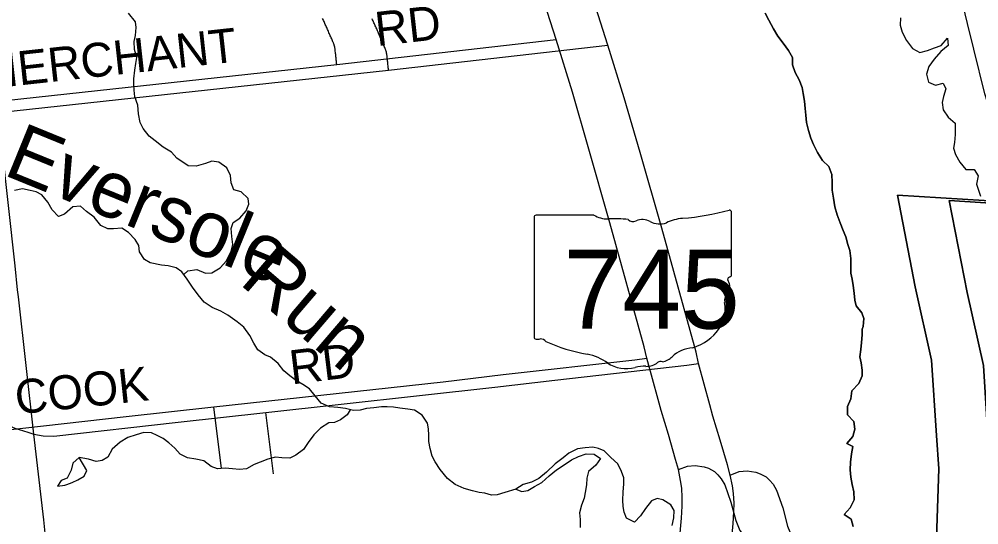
# Model space of a CAD drawing. Extents: x -38.2 to 41.9, y -4 to 24.9.
# Drawn here: x 2.823 to 4.425, y 18.738 to 19.582 of the extents above; entities that cross this region are included whole.
import ezdxf

# ---------------------------------------------------------------- set-up
doc = ezdxf.new("R2010")
doc.units = 0
for name, color, linetype in [('GM_X_Interchange_Ramps', 7, 'Continuous'), ('GM_X_Major_Lake', 7, 'Continuous'), ('GM_X_Major_River', 7, 'Continuous'), ('GM_X_Minor_Lake', 7, 'Continuous'), ('GM_X_Minor_River', 7, 'Continuous'), ('GM_X_Minor_River_Text', 7, 'Continuous'), ('GM_X_State_Location', 7, 'Continuous'), ('GM_X_State_Route', 7, 'Continuous'), ('GM_X_State_Shield', 7, 'Continuous'), ('GM_X_Township_Road', 7, 'Continuous'), ('GM_X_Township_Road_Text', 7, 'Continuous')]:
    doc.layers.add(name, color=color, linetype=linetype)

msp = doc.modelspace()

# ---------------------------------------------------------------- linework, layer by layer
at = {"layer": 'GM_X_Interchange_Ramps'}
for points in [[(8.9, 20.9), (5.1243, 20.9), (5.0869, 20.3321), (5.0183, 19.2401), (4.524, 19.2724), (4.5063, 19.2749), (4.2891, 19.2883), (4.3187, 19.1351), (4.3461, 19.0129), (4.3543, 18.8869), (4.3579, 18.8315), (4.3427, 18.3695), (4.3427, 18.2191), (4.3507, 18.0744), (4.3697, 17.9734), (4.4043, 17.861), (4.5071, 17.5648), (4.5129, 17.5446), (4.531, 17.482), (4.5322, 17.4318), (4.517, 17.3994), (4.4957, 17.354), (4.5219, 17.2005)], [(8.9, 20.9), (5.2114, 20.9), (5.1734, 20.3229), (5.1048, 19.2309), (4.6105, 19.2632), (4.5928, 19.2657), (4.3756, 19.2791), (4.4052, 19.1259), (4.4326, 19.0037), (4.4408, 18.8777), (4.4444, 18.8223), (4.4292, 18.3603), (4.4292, 18.2099), (4.4372, 18.0652), (4.4562, 17.9642), (4.4908, 17.8518), (4.5935, 17.5556), (4.5994, 17.5354), (4.6175, 17.4728), (4.6186, 17.4226), (4.6035, 17.3903), (4.5821, 17.3448), (4.6084, 17.1913)], [(4.5219, 17.2005), (4.4957, 17.354), (4.517, 17.3994), (4.5322, 17.4318), (4.531, 17.482), (4.5129, 17.5446), (4.5071, 17.5648), (4.4043, 17.861), (4.3697, 17.9734), (4.3507, 18.0744), (4.3427, 18.2191), (4.3427, 18.3695), (4.3579, 18.8315), (4.3543, 18.8869), (4.3461, 19.0129), (4.3187, 19.1351), (4.2891, 19.2883), (4.5063, 19.2749), (4.524, 19.2724), (5.0183, 19.2401), (5.0869, 20.3321)], [(4.6084, 17.1913), (4.5821, 17.3448), (4.6035, 17.3903), (4.6186, 17.4226), (4.6175, 17.4728), (4.5994, 17.5354), (4.5935, 17.5556), (4.4908, 17.8518), (4.4562, 17.9642), (4.4372, 18.0652), (4.4292, 18.2099), (4.4292, 18.3603), (4.4444, 18.8223), (4.4408, 18.8777), (4.4326, 19.0037), (4.4052, 19.1259), (4.3756, 19.2791), (4.5928, 19.2657), (4.6105, 19.2632), (5.1048, 19.2309), (5.1734, 20.3229)], [(3.9757, 18.9381), (3.9569, 19.007), (3.9527, 19.026), (3.8955, 19.2331), (3.8592, 19.3597), (3.8326, 19.4508), (3.8055, 19.539), (3.714, 19.8259), (3.6685, 19.9614), (3.651, 20.0166), (3.6474, 20.0308), (3.6447, 20.045), (3.636, 20.0869), (3.6248, 20.1343), (3.61, 20.2076), (3.6064, 20.2246), (3.6031, 20.2385), (3.5987, 20.261), (3.5926, 20.2977)], [(3.9994, 18.3639), (3.9915, 18.4341), (3.9915, 18.4746), (3.9931, 18.514), (4.0114, 18.7026), (4.0149, 18.7399), (4.0161, 18.7595), (4.0162, 18.7742), (4.0153, 18.7899), (4.0135, 18.8027), (4.0097, 18.8208), (4.005, 18.8379), (3.9931, 18.8793), (3.9808, 18.9194), (3.9757, 18.9381)]]:
    msp.add_lwpolyline(points, dxfattribs=at)
at = {"layer": 'GM_X_Major_Lake'}
for points in [[(4.2319, 19.0689), (4.2327, 19.0822), (4.2297, 19.0917), (4.2203, 19.1035), (4.2177, 19.113), (4.2166, 19.1244), (4.2151, 19.1377), (4.2133, 19.1479), (4.2114, 19.1578), (4.2111, 19.1691), (4.2112, 19.1824), (4.2093, 19.1961), (4.2063, 19.2059), (4.2026, 19.2188), (4.1985, 19.2291), (4.1932, 19.242), (4.1883, 19.2557), (4.1846, 19.269), (4.182, 19.2834), (4.1801, 19.2967), (4.1798, 19.3092), (4.1795, 19.3228), (4.1743, 19.3361), (4.1637, 19.3464), (4.1557, 19.3597), (4.149, 19.373), (4.1445, 19.3832), (4.1407, 19.3965), (4.1374, 19.4098), (4.1359, 19.4219), (4.1348, 19.4329), (4.1341, 19.4454), (4.1315, 19.4583), (4.1297, 19.4682), (4.1252, 19.4807), (4.1184, 19.4929), (4.1139, 19.5058), (4.1136, 19.5179), (4.1072, 19.5297), (4.0985, 19.5423), (4.0894, 19.554), (4.0819, 19.5662), (4.0743, 19.5803), (4.0683, 19.592)], [(4.2939, 19.5845), (4.2934, 19.572), (4.2968, 19.5603), (4.3043, 19.5466), (4.3142, 19.5333), (4.3263, 19.5264), (4.3392, 19.5298), (4.351, 19.5343), (4.362, 19.538), (4.3727, 19.5505), (4.3738, 19.5383), (4.3616, 19.5281), (4.3502, 19.5153), (4.3414, 19.5032), (4.3375, 19.4904), (4.3409, 19.4767), (4.3526, 19.4717), (4.3652, 19.4751), (4.3701, 19.4656), (4.3662, 19.4531), (4.3639, 19.4432), (4.3653, 19.4307), (4.374, 19.4186), (4.3857, 19.4087), (4.3853, 19.3992), (4.3857, 19.3893), (4.3845, 19.3764), (4.3825, 19.3666), (4.3859, 19.3564), (4.3934, 19.3434), (4.4032, 19.3309), (4.4169, 19.3312), (4.4237, 19.3205), (4.421, 19.3069), (4.4277, 19.2864)], [(4.2152, 18.7349), (4.2119, 18.747), (4.2001, 18.7551), (4.2101, 18.7664), (4.2166, 18.7796), (4.2163, 18.7929), (4.2133, 18.8054), (4.2114, 18.8172), (4.21, 18.8294), (4.2108, 18.8426), (4.2124, 18.8563), (4.2147, 18.8684), (4.2048, 18.8734), (4.2144, 18.8851), (4.2179, 18.8976), (4.2164, 18.9101), (4.2058, 18.9215), (4.2055, 18.9356), (4.2112, 18.9484), (4.2128, 18.9617), (4.2243, 18.9738), (4.23, 18.9867), (4.2304, 18.9961), (4.2286, 19.0083), (4.2264, 19.0182), (4.2279, 19.0303), (4.2288, 19.0424), (4.2299, 19.0549), (4.23, 19.0644), (4.2319, 19.0689)]]:
    msp.add_lwpolyline(points, dxfattribs=at)
at = {"layer": 'GM_X_Major_River'}
for points in [[(4.0683, 19.592), (4.0743, 19.5803), (4.0819, 19.5662), (4.0894, 19.554), (4.0985, 19.5423), (4.1072, 19.5297), (4.1136, 19.5179), (4.1139, 19.5058), (4.1184, 19.4929), (4.1252, 19.4807), (4.1297, 19.4682), (4.1315, 19.4583), (4.1341, 19.4454), (4.1348, 19.4329), (4.1359, 19.4219), (4.1374, 19.4098), (4.1407, 19.3965), (4.1445, 19.3832), (4.149, 19.373), (4.1557, 19.3597), (4.1637, 19.3464), (4.1743, 19.3361), (4.1795, 19.3228), (4.1798, 19.3092), (4.1801, 19.2967), (4.182, 19.2834), (4.1846, 19.269), (4.1883, 19.2557), (4.1932, 19.242), (4.1985, 19.2291), (4.2026, 19.2188), (4.2063, 19.2059), (4.2093, 19.1961), (4.2112, 19.1824), (4.2111, 19.1691), (4.2114, 19.1578), (4.2133, 19.1479), (4.2151, 19.1377), (4.2166, 19.1244), (4.2177, 19.113), (4.2203, 19.1035), (4.2297, 19.0917), (4.2327, 19.0822), (4.2319, 19.0689)], [(4.2939, 19.5845), (4.2934, 19.572), (4.2968, 19.5603), (4.3043, 19.5466), (4.3142, 19.5333), (4.3263, 19.5264), (4.3392, 19.5298), (4.351, 19.5343), (4.362, 19.538), (4.3727, 19.5505), (4.3738, 19.5383), (4.3616, 19.5281), (4.3502, 19.5153), (4.3414, 19.5032), (4.3375, 19.4904), (4.3409, 19.4767), (4.3526, 19.4717), (4.3652, 19.4751), (4.3701, 19.4656), (4.3662, 19.4531), (4.3639, 19.4432), (4.3653, 19.4307), (4.374, 19.4186), (4.3857, 19.4087), (4.3853, 19.3992), (4.3857, 19.3893), (4.3845, 19.3764), (4.3825, 19.3666), (4.3859, 19.3564), (4.3934, 19.3434), (4.4032, 19.3309), (4.4169, 19.3312), (4.4237, 19.3205), (4.421, 19.3069), (4.4277, 19.2864)], [(4.2319, 19.0689), (4.23, 19.0644), (4.2299, 19.0549), (4.2288, 19.0424), (4.2279, 19.0303), (4.2264, 19.0182), (4.2286, 19.0083), (4.2304, 18.9961), (4.23, 18.9867), (4.2243, 18.9738), (4.2128, 18.9617), (4.2112, 18.9484), (4.2055, 18.9356), (4.2058, 18.9215), (4.2164, 18.9101), (4.2179, 18.8976), (4.2144, 18.8851), (4.2048, 18.8734), (4.2147, 18.8684), (4.2124, 18.8563), (4.2108, 18.8426), (4.21, 18.8294), (4.2114, 18.8172), (4.2133, 18.8054), (4.2163, 18.7929), (4.2166, 18.7796), (4.2101, 18.7664), (4.2001, 18.7551), (4.2119, 18.747), (4.2152, 18.7349)], [(3.9127, 18.7368), (3.9158, 18.7493), (3.9162, 18.7618), (3.9105, 18.7713), (3.8973, 18.7797), (3.8878, 18.782), (3.8783, 18.7779), (3.8684, 18.765), (3.86, 18.7529), (3.8497, 18.7423), (3.8368, 18.7492), (3.8327, 18.759), (3.8308, 18.7685), (3.8304, 18.7792), (3.8312, 18.7921), (3.832, 18.8061), (3.8321, 18.8163), (3.8283, 18.827), (3.8219, 18.8399), (3.8105, 18.8505), (3.7995, 18.8612), (3.7901, 18.865), (3.7802, 18.8677), (3.7677, 18.8666), (3.7548, 18.8647), (3.7403, 18.8572), (3.7308, 18.8496), (3.7175, 18.8394), (3.703, 18.8258), (3.6901, 18.8152), (3.6779, 18.8088), (3.6639, 18.8054), (3.6517, 18.7975), (3.6619, 18.7937), (3.6718, 18.7952), (3.6828, 18.8016), (3.695, 18.8084), (3.7076, 18.8197), (3.7197, 18.8299), (3.7323, 18.8379), (3.7448, 18.8462), (3.7566, 18.8518), (3.7692, 18.8564), (3.7824, 18.8556), (3.7934, 18.8487), (3.7854, 18.8373), (3.7729, 18.8271), (3.7702, 18.8158), (3.7698, 18.8044), (3.7678, 18.7919), (3.7659, 18.7824), (3.7617, 18.7706), (3.7579, 18.7581), (3.759, 18.7467), (3.7593, 18.7331)]]:
    msp.add_lwpolyline(points, dxfattribs=at)
at = {"layer": 'GM_X_Minor_Lake'}
for points in [[(2.9226, 18.8504), (2.9119, 18.841), (2.9092, 18.8292), (2.9027, 18.8159), (2.8928, 18.8118), (2.8863, 18.8023), (2.8989, 18.8042), (2.9021, 18.8053)], [(2.9021, 18.8053), (2.911, 18.8083), (2.9205, 18.8129), (2.9308, 18.8193), (2.9354, 18.8288), (2.9226, 18.8504)]]:
    msp.add_lwpolyline(points, dxfattribs=at)
at = {"layer": 'GM_X_Minor_River'}
for points in [[(3.0974, 19.1558), (3.1042, 19.1621), (3.1193, 19.1639), (3.1334, 19.1582), (3.1444, 19.1586), (3.1581, 19.1669), (3.1687, 19.1786), (3.1764, 19.1949), (3.1791, 19.2059), (3.1776, 19.2195), (3.1765, 19.2324), (3.1796, 19.2426), (3.191, 19.2498), (3.2016, 19.2623), (3.2062, 19.2733), (3.2047, 19.2828), (3.193, 19.2938), (3.1809, 19.2972), (3.1767, 19.3086), (3.1756, 19.3211), (3.1692, 19.3337), (3.1559, 19.3436), (3.1442, 19.3451), (3.1335, 19.3414), (3.118, 19.3369), (3.1047, 19.3373), (3.0857, 19.3502), (3.077, 19.3601), (3.063, 19.3685), (3.0494, 19.3788), (3.0395, 19.3868), (3.0297, 19.3997), (3.0244, 19.4095), (3.0218, 19.424), (3.0207, 19.4388), (3.0158, 19.4524), (3.0143, 19.4634), (3.014, 19.4733), (3.014, 19.4828), (3.0156, 19.4972), (3.0171, 19.5081), (3.0187, 19.518), (3.0149, 19.5313), (3.0146, 19.5449), (3.0169, 19.5548), (3.0177, 19.568), (3.0166, 19.5779), (3.0052, 19.5923)], [(3.6517, 18.7975), (3.6334, 18.7919), (3.6205, 18.7881), (3.611, 18.7874), (3.6, 18.7908), (3.5905, 18.7916), (3.5792, 18.7947), (3.5655, 18.7985), (3.5503, 18.805), (3.5375, 18.8153), (3.5257, 18.8301), (3.517, 18.843), (3.5121, 18.8525), (3.5087, 18.8654), (3.5065, 18.8772), (3.5065, 18.8875), (3.5058, 18.8981), (3.5043, 18.9076), (3.4956, 18.9209), (3.4827, 18.9293), (3.4714, 18.9312), (3.4581, 18.9327), (3.4478, 18.9343), (3.4372, 18.9347), (3.4273, 18.9347), (3.4148, 18.9332), (3.4026, 18.9321), (3.392, 18.9291), (3.3806, 18.9288), (3.3673, 18.9319), (3.3544, 18.9338), (3.3408, 18.9346), (3.3267, 18.9411), (3.3169, 18.9532), (3.3071, 18.9647), (3.2961, 18.9719), (3.2858, 18.9784), (3.2745, 18.9864), (3.2643, 18.9951), (3.2552, 19.0073), (3.2423, 19.0176), (3.2328, 19.0214), (3.2211, 19.0301), (3.2143, 19.0412), (3.2079, 19.0537), (3.1977, 19.0678), (3.1863, 19.0769), (3.1711, 19.0879), (3.159, 19.0944), (3.145, 19.1005), (3.1313, 19.1097), (3.1211, 19.1218), (3.1117, 19.1344), (3.103, 19.1481), (3.0943, 19.1602), (3.0848, 19.1667), (3.0712, 19.1701), (3.0601, 19.1713), (3.0412, 19.1752), (3.0317, 19.1809), (3.0234, 19.1934), (3.0223, 19.2044), (3.0162, 19.2143), (3.0049, 19.2261), (2.9939, 19.2333), (2.9798, 19.2322), (2.9704, 19.2322), (2.9586, 19.2376), (2.9476, 19.2516), (2.9348, 19.2612), (2.9249, 19.2699), (2.912, 19.2688), (2.8979, 19.2567), (2.888, 19.2526), (2.8774, 19.2636), (2.8703, 19.2765), (2.8604, 19.2887), (2.8506, 19.2936), (2.8411, 19.2963), (2.8278, 19.2986), (2.8149, 19.296)], [(3.3754, 18.93), (3.3703, 18.9216), (3.3589, 18.9129), (3.349, 18.9088), (3.3396, 18.908), (3.3259, 18.8994), (3.3144, 18.888), (3.3053, 18.8751), (3.2973, 18.8638), (3.2844, 18.8539), (3.2745, 18.849), (3.2612, 18.8498), (3.2506, 18.851), (3.2376, 18.8472), (3.2247, 18.8427), (3.2148, 18.8386), (3.2019, 18.8314), (3.1905, 18.8303), (3.1787, 18.8311), (3.1666, 18.8327), (3.1537, 18.8315), (3.1431, 18.8354), (3.1306, 18.8445), (3.1173, 18.8476), (3.1033, 18.8495), (3.0911, 18.856), (3.0824, 18.8659), (3.0722, 18.875), (3.0627, 18.8819), (3.0529, 18.8868), (3.0434, 18.8914), (3.0305, 18.8918), (3.0179, 18.8881), (3.0039, 18.8836), (2.991, 18.8756), (2.978, 18.8643), (2.9704, 18.851), (2.9609, 18.845), (2.951, 18.8435), (2.9385, 18.8473), (2.9226, 18.8504)]]:
    msp.add_lwpolyline(points, dxfattribs=at)
at = {"layer": 'GM_X_State_Location'}
msp.add_line((3.247, 18.8228), (3.2343, 18.9256), dxfattribs=at)
for points in [[(3.4393, 19.4971), (3.4391, 19.499), (3.4389, 19.5008), (3.4387, 19.5027), (3.4385, 19.5045), (3.4383, 19.5064), (3.4381, 19.5082), (3.4379, 19.5101), (3.4377, 19.5119), (3.4375, 19.5138), (3.4373, 19.5156), (3.4371, 19.5175), (3.4369, 19.5193), (3.4367, 19.5212), (3.4366, 19.522), (3.4365, 19.5227), (3.4364, 19.5235), (3.4362, 19.5243), (3.4361, 19.5251), (3.4359, 19.5259), (3.4357, 19.5267), (3.4356, 19.5274), (3.4354, 19.5282), (3.4351, 19.529), (3.4349, 19.5297), (3.4347, 19.5305), (3.4344, 19.5313), (3.4342, 19.532), (3.4339, 19.5328), (3.4336, 19.5335), (3.4333, 19.5342), (3.433, 19.535), (3.4322, 19.5367), (3.4315, 19.5384), (3.4307, 19.5401), (3.43, 19.5418), (3.4292, 19.5435), (3.4285, 19.5452), (3.4277, 19.547), (3.427, 19.5487), (3.4262, 19.5504), (3.4255, 19.5521), (3.4247, 19.5538), (3.424, 19.5555), (3.4232, 19.5572), (3.4225, 19.5589), (3.4217, 19.5607), (3.421, 19.5624), (3.4202, 19.5641), (3.4195, 19.5658), (3.4187, 19.5675), (3.4179, 19.5692), (3.4172, 19.5709), (3.4164, 19.5726), (3.4157, 19.5744), (3.4149, 19.5761), (3.4142, 19.5778), (3.4134, 19.5795), (3.4127, 19.5812), (3.4119, 19.5829)], [(2.7879, 19.4263), (3.4393, 19.4971), (3.8055, 19.539)], [(2.8369, 18.8925), (2.8472, 18.8892), (2.8627, 18.8862), (2.8804, 18.8861), (3.0878, 18.9093), (3.2343, 18.9256), (3.6167, 18.9676), (3.7172, 18.9796), (3.9373, 19.0042), (3.9569, 19.007)], [(2.2247, 18.8879), (2.4016, 18.8979), (2.5637, 18.908), (2.6354, 18.9114), (2.7568, 18.9192), (2.7699, 18.918), (2.8152, 18.8993), (2.8369, 18.8925)], [(2.902, 18.3636), (2.8777, 18.607), (2.8636, 18.7461), (2.8472, 18.8892)], [(4.0097, 18.8208), (4.0249, 18.8267), (4.038, 18.8278), (4.0526, 18.8257), (4.0599, 18.8232), (4.0698, 18.8177), (4.0756, 18.8123), (4.0813, 18.8056), (4.0873, 18.7955), (4.0975, 18.7663), (4.1057, 18.7356), (4.1124, 18.7193), (4.1194, 18.7098), (4.1246, 18.7041), (4.1408, 18.6958), (4.1514, 18.6925), (4.1606, 18.6923), (4.1668, 18.6935), (4.1839, 18.6965), (4.2381, 18.709)]]:
    msp.add_lwpolyline(points, dxfattribs=at)
at = {"layer": 'GM_X_State_Route'}
for points in [[(3.8893, 18.9473), (3.8705, 19.0162), (3.8662, 19.0352), (3.809, 19.2422), (3.7727, 19.3689), (3.7462, 19.46), (3.7191, 19.5482), (3.6275, 19.835), (3.582, 19.9706), (3.5645, 20.0257), (3.561, 20.04), (3.5582, 20.0542), (3.5495, 20.0961), (3.5384, 20.1435), (3.5235, 20.2168), (3.5199, 20.2338), (3.5166, 20.2477), (3.5122, 20.2701), (3.5061, 20.3069)], [(4.509, 19.2678), (4.5065, 19.2743), (4.4936, 19.3077), (4.4567, 19.3976), (4.4441, 19.4295), (4.4349, 19.4577), (4.4165, 19.5318), (4.4058, 19.575), (4.3912, 19.6379), (4.3834, 19.6683), (4.3767, 19.6899), (4.3618, 19.7292), (4.3373, 19.7759), (4.329, 19.7891), (4.3152, 19.8064), (4.2941, 19.831), (4.2289, 19.8876)], [(3.9129, 18.3731), (3.905, 18.4433), (3.905, 18.4838), (3.9067, 18.5232), (3.925, 18.7118), (3.9284, 18.7491), (3.9296, 18.7687), (3.9298, 18.7833), (3.9288, 18.7991), (3.927, 18.8119), (3.9233, 18.83), (3.9185, 18.8471), (3.9066, 18.8885), (3.8944, 18.9286), (3.8893, 18.9473)]]:
    msp.add_lwpolyline(points, dxfattribs=at)
at = {"layer": 'GM_X_State_Shield'}
for p, q in [((3.6825, 19.2515), (3.6825, 19.0514)), ((3.7822, 19.2549), (3.6857, 19.2549)), ((4.0121, 19.1552), (4.0121, 19.2599)), ((4.012, 19.1552), (4.0121, 19.1552))]:
    msp.add_line(p, q, dxfattribs=at)
for centre, major_axis, start_param, end_param in [((3.8947, 19.5278), (0.3495, 0), 4.814394, 5.042369), ((4.0084, 19.2603), (0.00367, 0), 6.141152, 7.989035), ((3.6863, 19.2519), (0.00382, 0), 1.712693, 3.28349), ((3.8052, 19.2782), (0.037, 0), 4.042523, 4.731795), ((3.8175, 19.1426), (0.133, 0), 1.404758, 1.657858), ((3.8477, 19.2529), (0.0107, 0), 3.836095, 5.185415), ((3.8634, 19.2298), (0.0222, 0), 0.950623, 2.079405), ((3.9392, 19.1938), (0.0703, 0), 1.699011, 2.107814), ((3.892, 19.2615), (0.0267, 0), 4.081561, 5.145723), ((4.0112, 19.1475), (0.00568, 0), 1.883978, 3.671073), ((4.0081, 19.1548), (0.00393, 0), 5.05454, 6.418171), ((3.9751, 19.1343), (0.0341, 0), 5.934695, 6.695948), ((4.0252, 19.1114), (0.0248, 0), 2.387724, 3.262537), ((3.9142, 19.0981), (0.0874, 0), 5.101752, 6.440018), ((3.6863, 19.0509), (0.00385, 0), 3.00124, 4.508301), ((3.6869, 19.0714), (0.0294, 0), 4.665946, 4.897461), ((3.6929, 19.0398), (0.0106, 0), 0.519207, 1.627899), ((3.8267, 19.2196), (0.2524, 0), 4.195997, 4.488961), ((3.7515, 18.9615), (0.079, 0), 0.823519, 1.323587), ((3.9511, 18.9952), (0.0479, 0), 1.647645, 2.488434), ((3.8369, 19.0388), (0.0501, 0), 4.026481, 4.996735), ((3.8695, 19.0238), (0.0267, 0), 4.691044, 5.507374), ((3.8936, 19.0045), (0.00752, 0), 1.147584, 2.315152), ((3.8904, 19.032), (0.0282, 0), 4.937069, 5.64225), ((3.8658, 18.9696), (0.0412, 0), 1.495662, 1.94098)]:
    msp.add_ellipse(centre, major_axis=major_axis, ratio=0.8, start_param=start_param, end_param=end_param, dxfattribs=at)
at = {"layer": 'GM_X_Township_Road'}
msp.add_line((3.1605, 18.832), (3.1478, 18.9348), dxfattribs=at)
for points in [[(3.3529, 19.5063), (3.3526, 19.5082), (3.3524, 19.51), (3.3522, 19.5118), (3.352, 19.5137), (3.3518, 19.5156), (3.3516, 19.5174), (3.3514, 19.5192), (3.3512, 19.5211), (3.351, 19.523), (3.3508, 19.5248), (3.3506, 19.5266), (3.3504, 19.5285), (3.3502, 19.5304), (3.3501, 19.5311), (3.35, 19.5319), (3.3499, 19.5327), (3.3497, 19.5335), (3.3496, 19.5343), (3.3494, 19.5351), (3.3493, 19.5358), (3.3491, 19.5366), (3.3489, 19.5374), (3.3487, 19.5382), (3.3484, 19.5389), (3.3482, 19.5397), (3.3479, 19.5404), (3.3477, 19.5412), (3.3474, 19.5419), (3.3471, 19.5427), (3.3468, 19.5434), (3.3465, 19.5442), (3.3458, 19.5459), (3.345, 19.5476), (3.3443, 19.5493), (3.3435, 19.551), (3.3427, 19.5527), (3.342, 19.5544), (3.3412, 19.5561), (3.3405, 19.5579), (3.3397, 19.5596), (3.339, 19.5613), (3.3382, 19.563), (3.3375, 19.5647), (3.3367, 19.5664), (3.336, 19.5681), (3.3352, 19.5698), (3.3345, 19.5716), (3.3337, 19.5733), (3.333, 19.575), (3.3322, 19.5767), (3.3315, 19.5784), (3.3307, 19.5801), (3.33, 19.5818), (3.3292, 19.5835)], [(2.7015, 19.4355), (3.3529, 19.5063), (3.7191, 19.5482)], [(2.7504, 18.9017), (2.7607, 18.8984), (2.7762, 18.8953), (2.7939, 18.8953), (3.0014, 18.9185), (3.1478, 18.9348), (3.5303, 18.9768), (3.6307, 18.9888), (3.8508, 19.0134), (3.8705, 19.0162)], [(3.9233, 18.83), (3.9385, 18.8359), (3.9515, 18.837), (3.9662, 18.8349), (3.9734, 18.8324), (3.9833, 18.8269), (3.9892, 18.8214), (3.9948, 18.8148), (4.0009, 18.8047), (4.0111, 18.7755), (4.0192, 18.7448), (4.0259, 18.7285), (4.0329, 18.719), (4.0381, 18.7133), (4.0544, 18.705), (4.065, 18.7017), (4.0741, 18.7015), (4.0803, 18.7027), (4.0974, 18.7056), (4.1516, 18.7182)]]:
    msp.add_lwpolyline(points, dxfattribs=at)
at = {"layer": 'GM_X_Township_Road_Text'}
msp.add_lwpolyline([(2.8472, 18.8892), (2.8216, 19.1185), (2.8198, 19.1301), (2.8156, 19.1701), (2.7934, 19.372), (2.7879, 19.4263)], dxfattribs=at)

# ---------------------------------------------------------------- texts
at = {"layer": 'GM_X_Minor_River_Text'}
for s, height, rotation, p in [('Eversole', 0.09466, 337.8033, (2.7938, 19.3231)), ('Run', 0.09463, 319.4281, (3.1881, 19.1414))]:
    msp.add_text(s, height=height, rotation=rotation, dxfattribs=at).set_placement(p)
at = {"layer": 'GM_X_State_Location'}
for s in ['s', 'r']:
    msp.add_text(s, height=0.000189, dxfattribs=at).set_placement((3.8436, 19.1381))
msp.add_text('745', height=0.000189, rotation=0, dxfattribs=at).set_placement((3.7767, 19.1243))
at = {"layer": 'GM_X_State_Shield'}
msp.add_text('745', height=0.13184, dxfattribs=at).set_placement((3.7316, 19.0655))
at = {"layer": 'GM_X_Township_Road_Text'}
for s, rotation, p in [('RD', 6.4498, (3.42, 19.5371)), ('MERCHANT', 6.2594, (2.7601, 19.4646)), ('RD', 6.9409, (3.2773, 18.9721)), ('COOK', 6.0977, (2.8185, 18.9221))]:
    msp.add_text(s, height=0.05682, rotation=rotation, dxfattribs=at).set_placement(p)

doc.saveas('drawing.dxf')
